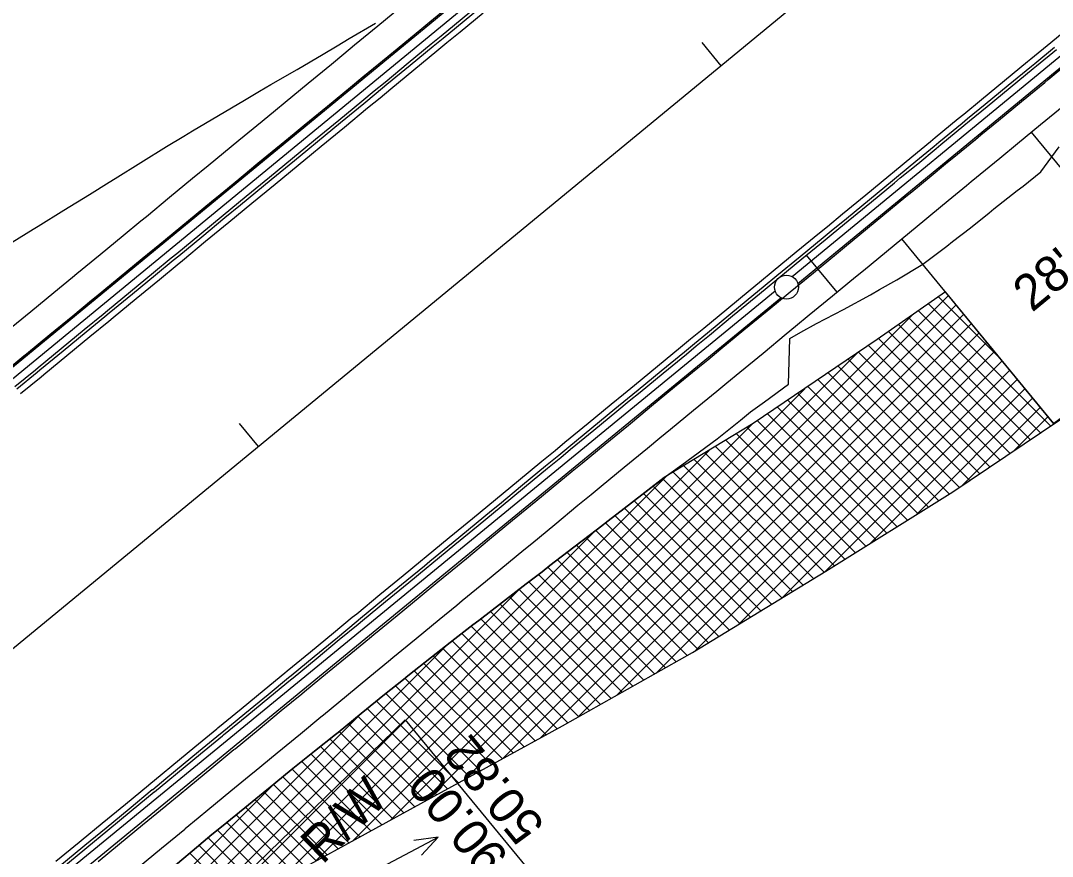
# Model space of a CAD drawing. Extents: x 1147550 to 1149124, y 2017436 to 2018779.
# Drawn here: x 1148734.8 to 1148907, y 2018327.9 to 2018467.3 of the extents above; entities that cross this region are included whole.
import ezdxf

# ---------------------------------------------------------------- set-up
doc = ezdxf.new("R2010")
doc.units = 0
for name, color, linetype in [('S_EDGE_CONCRETE', 7, 'Continuous'), ('S_ELECTRIC_UTILITIES', 7, 'Continuous'), ('S_HEADWALL', 7, 'Continuous'), ('S_IRON_PIN_ANNOT', 7, 'Continuous'), ('S_MAILBOX', 7, 'Continuous'), ('S_SECONDARY_CTL', 7, 'Continuous'), ('S_TANK', 7, 'Continuous'), ('S_TELEPHONE_UTILITIES', 7, 'Continuous'), ('S_TELEPHONE_UTILITIES_ANNOT', 7, 'Continuous')]:
    doc.layers.add(name, color=color, linetype=linetype)

msp = doc.modelspace()

# ---------------------------------------------------------------- linework, layer by layer
at = {"layer": 'S_EDGE_CONCRETE'}
msp.add_line((1148677.53, 2018316.54), (1149083.36, 2018650.43), dxfattribs=at)
for points in [[(1148848.51, 2018463.68), (1148851.69, 2018459.82)], [(1148771.29, 2018400.15), (1148774.47, 2018396.29)]]:
    msp.add_lwpolyline(points, dxfattribs=at)
at = {"layer": 'S_ELECTRIC_UTILITIES'}
msp.add_lwpolyline([(1148799.03, 2018350.69), (1148821.27, 2018323.67)], dxfattribs=at)
at = {"layer": 'S_HEADWALL'}
for p, q in [((1148929.92, 2018416.68), (1148903.54, 2018448.74)), ((1148907.31, 2018400.08), (1148881.92, 2018430.95)), ((1148871.11, 2018422.06), (1148866.02, 2018428.24))]:
    msp.add_line(p, q, dxfattribs=at)
at = {"layer": 'S_IRON_PIN_ANNOT'}
for p, q in [((1148809, 2018340.74), (1148889.72, 2018421.47)), ((1148888.02, 2018421.28), (1148898.48, 2018410.82)), ((1148815.26, 2018344.17), (1148891, 2018419.91)), ((1148884.69, 2018418.95), (1148905.07, 2018398.57)), ((1148886.36, 2018420.12), (1148906.76, 2018399.71)), ((1148802.75, 2018337.32), (1148883.66, 2018418.23)), ((1148821.51, 2018347.59), (1148892.28, 2018418.36)), ((1148827.86, 2018351.11), (1148893.55, 2018416.81)), ((1148883.03, 2018417.79), (1148903.38, 2018397.43)), ((1148834.35, 2018354.78), (1148894.83, 2018415.26)), ((1148879.7, 2018415.46), (1148900.01, 2018395.15)), ((1148881.36, 2018416.62), (1148901.7, 2018396.29)), ((1148840.85, 2018358.44), (1148896.11, 2018413.71)), ((1148878.04, 2018414.29), (1148898.32, 2018394.01)), ((1148796.51, 2018333.91), (1148874.48, 2018411.88)), ((1148847.38, 2018362.15), (1148897.38, 2018412.15)), ((1148874.67, 2018412.01), (1148894.94, 2018391.73)), ((1148876.35, 2018413.15), (1148896.63, 2018392.87)), ((1148854.65, 2018366.6), (1148898.66, 2018410.6)), ((1148872.98, 2018410.86), (1148893.25, 2018390.6)), ((1148861.92, 2018371.04), (1148899.94, 2018409.05)), ((1148869.61, 2018408.58), (1148889.85, 2018388.34)), ((1148871.3, 2018409.72), (1148891.56, 2018389.46)), ((1148867.93, 2018407.43), (1148888.11, 2018387.25)), ((1148869.2, 2018375.48), (1148901.21, 2018407.5)), ((1148790.27, 2018330.5), (1148865.7, 2018405.92)), ((1148864.55, 2018405.15), (1148884.62, 2018385.08)), ((1148866.24, 2018406.29), (1148886.37, 2018386.17)), ((1148876.68, 2018380.14), (1148902.49, 2018405.95)), ((1148862.87, 2018404.01), (1148882.88, 2018384)), ((1148884.17, 2018384.8), (1148903.77, 2018404.4)), ((1148859.5, 2018401.72), (1148879.39, 2018381.83)), ((1148861.18, 2018402.86), (1148881.14, 2018382.91)), ((1148891.85, 2018389.65), (1148905.04, 2018402.84)), ((1148900.54, 2018395.52), (1148906.32, 2018401.29)), ((1148784.04, 2018327.09), (1148856.95, 2018400.01)), ((1148857.81, 2018400.58), (1148877.65, 2018380.74)), ((1148854.32, 2018398.41), (1148874.16, 2018378.57)), ((1148856.08, 2018399.48), (1148875.91, 2018379.66)), ((1148850.8, 2018396.28), (1148870.67, 2018376.4)), ((1148852.56, 2018397.34), (1148872.42, 2018377.49)), ((1148777.91, 2018323.79), (1148849.77, 2018395.65)), ((1148849.04, 2018395.21), (1148868.93, 2018375.32)), ((1148845.52, 2018393.07), (1148865.42, 2018373.17)), ((1148847.28, 2018394.14), (1148867.17, 2018374.25)), ((1148771.86, 2018320.57), (1148842.58, 2018391.3)), ((1148842.02, 2018390.92), (1148861.91, 2018371.03)), ((1148843.76, 2018392.01), (1148863.66, 2018372.1)), ((1148840.41, 2018389.69), (1148860.15, 2018369.96)), ((1148838.81, 2018388.47), (1148858.4, 2018368.88)), ((1148835.62, 2018386), (1148854.88, 2018366.74)), ((1148837.22, 2018387.23), (1148856.64, 2018367.81)), ((1148834.02, 2018384.77), (1148853.13, 2018365.66)), ((1148832.43, 2018383.54), (1148851.37, 2018364.59)), ((1148765.8, 2018317.34), (1148830.54, 2018382.08)), ((1148829.23, 2018381.07), (1148847.86, 2018362.45)), ((1148830.83, 2018382.3), (1148849.62, 2018363.52)), ((1148827.64, 2018379.84), (1148846.08, 2018361.4)), ((1148824.44, 2018377.39), (1148842.46, 2018359.36)), ((1148826.04, 2018378.61), (1148844.27, 2018360.38)), ((1148822.84, 2018376.15), (1148840.66, 2018358.34)), ((1148821.25, 2018374.92), (1148838.85, 2018357.32)), ((1148759.75, 2018314.12), (1148818.22, 2018372.59)), ((1148818.05, 2018372.46), (1148835.23, 2018355.28)), ((1148819.65, 2018373.69), (1148837.04, 2018356.3)), ((1148816.45, 2018371.23), (1148833.42, 2018354.26)), ((1148813.25, 2018368.78), (1148829.81, 2018352.22)), ((1148814.85, 2018370), (1148831.62, 2018353.24)), ((1148811.65, 2018367.55), (1148828, 2018351.19)), ((1148810.05, 2018366.32), (1148826.19, 2018350.17)), ((1148806.86, 2018363.84), (1148822.55, 2018348.16)), ((1148808.45, 2018365.08), (1148824.37, 2018349.16)), ((1148753.78, 2018310.98), (1148805.84, 2018363.04)), ((1148805.28, 2018362.6), (1148820.72, 2018347.16)), ((1148802.12, 2018360.11), (1148817.06, 2018345.16)), ((1148803.7, 2018361.35), (1148818.89, 2018346.16)), ((1148800.53, 2018358.86), (1148815.24, 2018344.16)), ((1148798.95, 2018357.62), (1148813.41, 2018343.16)), ((1148795.82, 2018355.09), (1148809.75, 2018341.16)), ((1148797.39, 2018356.35), (1148811.58, 2018342.16)), ((1148794.26, 2018353.82), (1148807.93, 2018340.16)), ((1148747.82, 2018307.84), (1148791.81, 2018351.84)), ((1148792.7, 2018352.56), (1148806.1, 2018339.15)), ((1148789.57, 2018350.02), (1148802.44, 2018337.15)), ((1148791.13, 2018351.29), (1148804.27, 2018338.15)), ((1148788.01, 2018348.76), (1148800.61, 2018336.15)), ((1148784.88, 2018346.24), (1148796.96, 2018334.15)), ((1148786.44, 2018347.5), (1148798.79, 2018335.15)), ((1148783.31, 2018344.97), (1148795.13, 2018333.15)), ((1148781.75, 2018343.71), (1148793.3, 2018332.15)), ((1148778.62, 2018341.18), (1148789.64, 2018330.16)), ((1148780.18, 2018342.44), (1148791.47, 2018331.16)), ((1148741.85, 2018304.7), (1148777.05, 2018339.91)), ((1148777.06, 2018339.91), (1148787.81, 2018329.16)), ((1148775.5, 2018338.64), (1148785.98, 2018328.16)), ((1148772.38, 2018336.1), (1148782.33, 2018326.16)), ((1148773.94, 2018337.37), (1148784.16, 2018327.16)), ((1148770.82, 2018334.83), (1148780.49, 2018325.17)), ((1148769.26, 2018333.56), (1148778.64, 2018324.18)), ((1148766.15, 2018331.02), (1148774.95, 2018322.22)), ((1148767.7, 2018332.29), (1148776.8, 2018323.2)), ((1148764.61, 2018329.73), (1148773.11, 2018321.23)), ((1148763.08, 2018328.44), (1148771.26, 2018320.25))]:
    msp.add_line(p, q, dxfattribs=at)
for points in [[(1148725.05, 2018295.78), (1148737.29, 2018302.31), (1148759.39, 2018313.93), (1148781.46, 2018325.68), (1148803.37, 2018337.66), (1148825.28, 2018349.66), (1148846.98, 2018361.91), (1148869.23, 2018375.5), (1148890.45, 2018388.71), (1148911.17, 2018402.69), (1148932.43, 2018418.55), (1148951.91, 2018434.12), (1148970.58, 2018450.61), (1148989.32, 2018467.79), (1149007.56, 2018484.84), (1149025.52, 2018502.19), (1149043.36, 2018519.65), (1149061.14, 2018537.18), (1149078.8, 2018555.13), (1149096.46, 2018572.78), (1149114.15, 2018590.39), (1149117.96, 2018594.21)], [(1149031.17, 2018547.02), (1149027.18, 2018543.02), (1149009.16, 2018525.75), (1148991.23, 2018508.37), (1148972.44, 2018490.46), (1148954.61, 2018474.07), (1148935.64, 2018457.92), (1148916.42, 2018442.05), (1148911.86, 2018438.63), (1148929.89, 2018416.72), (1148907.28, 2018400.13), (1148889.2, 2018422.11), (1148877.8, 2018414.13), (1148857.12, 2018400.11), (1148842.25, 2018391.1)], [(1148842.25, 2018391.1), (1148839.04, 2018388.64), (1148835.08, 2018385.58), (1148833.39, 2018384.28), (1148831.12, 2018382.52), (1148827.15, 2018379.47), (1148823.18, 2018376.43), (1148821.87, 2018375.4), (1148819.23, 2018373.36), (1148815.26, 2018370.32), (1148811.29, 2018367.28), (1148810.34, 2018366.55), (1148807.33, 2018364.21), (1148803.4, 2018361.12), (1148799.47, 2018358.03), (1148798.73, 2018357.44), (1148795.58, 2018354.89), (1148791.69, 2018351.74), (1148787.81, 2018348.59), (1148787.37, 2018348.24), (1148783.91, 2018345.46), (1148780.02, 2018342.32), (1148776.14, 2018339.17), (1148775.95, 2018339.01), (1148772.27, 2018336.01), (1148768.39, 2018332.85), (1148766.77, 2018331.54), (1148764.6, 2018329.72), (1148764.53, 2018329.66), (1148760.71, 2018326.45)]]:
    msp.add_lwpolyline(points, dxfattribs=at)
at = {"layer": 'S_MAILBOX'}
msp.add_lwpolyline([(1147623.68, 2017436.42), (1147751.67, 2017548.43), (1147958.55, 2017704.02), (1148020.45, 2017753.36), (1148124.6, 2017828.73), (1148174.25, 2017853.51), (1148282.74, 2017941.53), (1148421.63, 2018031.39), (1148612.18, 2018197.22), (1148639.91, 2018214.06), (1148753.45, 2018306.48), (1148799.03, 2018350.69)], dxfattribs=at)
at = {"layer": 'S_SECONDARY_CTL'}
for points in [[(1148733.44, 2018430.41), (1148736.93, 2018432.55), (1148737.74, 2018433.06), (1148742.04, 2018435.7), (1148746.34, 2018438.35), (1148749.61, 2018440.37), (1148750.61, 2018441.02), (1148754.9, 2018443.68), (1148759.2, 2018446.32), (1148762.06, 2018448.09), (1148763.5, 2018448.97), (1148767.87, 2018451.53), (1148772.23, 2018454.1), (1148774.73, 2018455.58), (1148776.58, 2018456.67), (1148780.99, 2018459.19), (1148785.35, 2018461.76), (1148787.68, 2018463.15), (1148789.7, 2018464.34), (1148794.05, 2018466.92)], [(1148760.71, 2018326.45), (1148764.53, 2018329.66), (1148764.6, 2018329.72), (1148766.77, 2018331.54), (1148768.39, 2018332.85), (1148772.27, 2018336.01), (1148775.95, 2018339.01), (1148776.14, 2018339.17), (1148780.02, 2018342.32), (1148783.91, 2018345.46), (1148787.37, 2018348.24), (1148787.81, 2018348.59), (1148791.69, 2018351.74), (1148795.58, 2018354.89), (1148798.73, 2018357.44), (1148799.47, 2018358.03), (1148803.4, 2018361.12), (1148807.33, 2018364.21), (1148810.34, 2018366.55), (1148811.29, 2018367.28), (1148815.26, 2018370.32), (1148819.23, 2018373.36), (1148821.87, 2018375.4), (1148823.18, 2018376.43), (1148827.15, 2018379.47), (1148831.12, 2018382.52), (1148833.39, 2018384.28), (1148835.08, 2018385.58), (1148839.04, 2018388.64), (1148843.01, 2018391.68), (1148845.18, 2018393.26), (1148847.06, 2018394.63), (1148851.1, 2018397.58), (1148855.01, 2018400.7), (1148856.68, 2018402.05), (1148858.98, 2018403.74), (1148863.02, 2018406.71), (1148863.22, 2018414.33), (1148865.03, 2018415.35), (1148867.65, 2018416.82), (1148872.19, 2018419.16), (1148876.66, 2018421.61), (1148878.16, 2018422.47), (1148881.07, 2018424.12), (1148885.43, 2018426.69), (1148889.4, 2018429.73), (1148890.38, 2018430.48), (1148893.36, 2018432.78), (1148896.47, 2018435.3), (1148897.25, 2018435.93), (1148901.19, 2018439), (1148902.15, 2018439.73), (1148905.09, 2018442.14), (1148908.17, 2018446.27)]]:
    msp.add_lwpolyline(points, dxfattribs=at)
at = {"layer": 'S_TANK'}
for p, q in [((1148793.41, 2018325.23), (1148804.51, 2018331.13)), ((1148804.51, 2018331.13), (1148800.45, 2018330.56)), ((1148804.51, 2018331.13), (1148801.77, 2018328.09))]:
    msp.add_line(p, q, dxfattribs=at)
at = {"layer": 'S_TELEPHONE_UTILITIES'}
msp.add_line((1148654.34, 2018344.72), (1148896.46, 2018543.92), dxfattribs=at)
for points in [[(1148731.97, 2018408.59), (1148735.4, 2018411.41), (1148735.83, 2018411.77), (1148739.69, 2018414.95), (1148743.55, 2018418.12), (1148746.68, 2018420.7), (1148747.42, 2018421.3), (1148751.28, 2018424.48), (1148755.14, 2018427.65), (1148758.08, 2018430.07), (1148759, 2018430.83), (1148762.86, 2018434.01), (1148766.72, 2018437.18), (1148769.29, 2018439.3), (1148770.58, 2018440.36), (1148774.44, 2018443.54), (1148778.3, 2018446.71), (1148780.52, 2018448.54), (1148782.17, 2018449.89), (1148786.03, 2018453.07), (1148789.89, 2018456.24), (1148791.96, 2018457.95), (1148793.75, 2018459.42), (1148797.61, 2018462.6), (1148801.47, 2018465.77), (1148803.13, 2018467.14), (1148805.33, 2018468.95)], [(1148732.66, 2018415.63), (1148736.52, 2018418.81), (1148740.38, 2018421.98), (1148743.51, 2018424.56), (1148744.24, 2018425.16), (1148748.1, 2018428.34), (1148751.96, 2018431.51), (1148754.9, 2018433.93), (1148755.82, 2018434.69), (1148759.68, 2018437.87), (1148763.54, 2018441.04), (1148766.12, 2018443.16), (1148767.41, 2018444.22), (1148771.27, 2018447.4), (1148775.13, 2018450.57), (1148777.35, 2018452.4), (1148778.99, 2018453.75), (1148782.85, 2018456.93), (1148786.71, 2018460.1), (1148788.78, 2018461.81), (1148790.57, 2018463.28), (1148794.43, 2018466.46), (1148798.29, 2018469.63)], [(1148733.88, 2018406.28), (1148737.3, 2018409.09), (1148737.74, 2018409.45), (1148741.6, 2018412.63), (1148745.46, 2018415.81), (1148748.59, 2018418.38), (1148749.32, 2018418.98), (1148753.18, 2018422.16), (1148757.04, 2018425.34), (1148759.98, 2018427.75), (1148760.9, 2018428.51), (1148764.77, 2018431.69), (1148768.63, 2018434.87), (1148771.2, 2018436.98), (1148772.49, 2018438.04), (1148776.35, 2018441.22), (1148780.21, 2018444.4), (1148782.43, 2018446.22), (1148784.07, 2018447.57), (1148787.93, 2018450.75), (1148791.79, 2018453.93), (1148793.87, 2018455.63), (1148795.66, 2018457.1), (1148799.52, 2018460.28), (1148803.38, 2018463.46), (1148805.04, 2018464.82), (1148807.24, 2018466.63), (1148811.1, 2018469.81)], [(1148734.19, 2018405.89), (1148737.62, 2018408.71), (1148738.06, 2018409.07), (1148741.92, 2018412.24), (1148745.78, 2018415.42), (1148748.91, 2018417.99), (1148749.64, 2018418.6), (1148753.5, 2018421.77), (1148757.36, 2018424.95), (1148760.3, 2018427.37), (1148761.22, 2018428.13), (1148765.08, 2018431.3), (1148768.94, 2018434.48), (1148771.52, 2018436.6), (1148772.81, 2018437.66), (1148776.67, 2018440.83), (1148780.53, 2018444.01), (1148782.75, 2018445.84), (1148784.39, 2018447.19), (1148788.25, 2018450.36), (1148792.11, 2018453.54), (1148794.18, 2018455.24), (1148795.97, 2018456.72), (1148799.83, 2018459.89), (1148803.7, 2018463.07), (1148805.36, 2018464.44), (1148807.56, 2018466.25), (1148811.42, 2018469.42)], [(1148734.83, 2018405.12), (1148738.26, 2018407.94), (1148738.69, 2018408.29), (1148742.55, 2018411.47), (1148746.41, 2018414.65), (1148749.54, 2018417.22), (1148750.27, 2018417.82), (1148754.14, 2018421), (1148758, 2018424.18), (1148760.94, 2018426.6), (1148761.86, 2018427.35), (1148765.72, 2018430.53), (1148769.58, 2018433.71), (1148772.15, 2018435.82), (1148773.44, 2018436.88), (1148777.3, 2018440.06), (1148781.16, 2018443.24), (1148783.38, 2018445.06), (1148785.02, 2018446.41), (1148788.89, 2018449.59), (1148792.75, 2018452.77), (1148794.82, 2018454.47), (1148796.61, 2018455.94), (1148800.47, 2018459.12), (1148804.33, 2018462.3), (1148805.99, 2018463.67), (1148808.19, 2018465.47), (1148812.05, 2018468.65)], [(1148740.74, 2018327.1), (1148744.6, 2018330.28), (1148744.92, 2018330.54), (1148748.46, 2018333.46), (1148752.32, 2018336.63), (1148756.19, 2018339.81), (1148756.25, 2018339.86), (1148758.44, 2018341.67), (1148760.05, 2018342.99), (1148763.91, 2018346.16), (1148767.58, 2018349.19), (1148767.77, 2018349.34), (1148771.63, 2018352.52), (1148775.49, 2018355.69), (1148778.92, 2018358.51), (1148779.35, 2018358.87), (1148783.21, 2018362.05), (1148787.08, 2018365.22), (1148790.2, 2018367.8), (1148790.94, 2018368.4), (1148794.8, 2018371.58), (1148798.66, 2018374.75), (1148801.6, 2018377.17), (1148802.52, 2018377.93), (1148806.38, 2018381.11), (1148810.24, 2018384.29), (1148812.81, 2018386.4), (1148814.1, 2018387.46), (1148817.96, 2018390.64), (1148821.83, 2018393.82), (1148824.04, 2018395.64), (1148825.69, 2018396.99), (1148829.55, 2018400.17), (1148833.41, 2018403.35), (1148835.48, 2018405.05), (1148837.27, 2018406.52), (1148841.13, 2018409.7), (1148844.99, 2018412.88), (1148846.65, 2018414.24), (1148848.85, 2018416.05), (1148852.71, 2018419.23), (1148856.58, 2018422.41), (1148858.15, 2018423.7), (1148860.44, 2018425.58), (1148864.3, 2018428.76), (1148868.16, 2018431.94), (1148869.48, 2018433.02), (1148872.02, 2018435.11), (1148875.88, 2018438.29), (1148879.74, 2018441.47), (1148880.7, 2018442.25), (1148883.6, 2018444.64), (1148886.69, 2018447.18), (1148887.47, 2018447.82), (1148891.33, 2018451), (1148892.25, 2018451.76), (1148895.19, 2018454.17), (1148899.05, 2018457.35), (1148902.91, 2018460.53), (1148903.46, 2018460.98), (1148906.77, 2018463.7), (1148910.63, 2018466.88)], [(1148741.38, 2018326.33), (1148745.24, 2018329.51), (1148745.55, 2018329.77), (1148749.1, 2018332.69), (1148752.96, 2018335.86), (1148756.82, 2018339.04), (1148756.88, 2018339.09), (1148759.08, 2018340.89), (1148760.68, 2018342.22), (1148764.54, 2018345.39), (1148768.22, 2018348.41), (1148768.4, 2018348.57), (1148772.27, 2018351.75), (1148776.13, 2018354.92), (1148779.55, 2018357.74), (1148779.99, 2018358.1), (1148783.85, 2018361.28), (1148787.71, 2018364.45), (1148790.84, 2018367.03), (1148791.57, 2018367.63), (1148795.43, 2018370.81), (1148799.29, 2018373.98), (1148802.23, 2018376.4), (1148803.16, 2018377.16), (1148807.02, 2018380.34), (1148810.88, 2018383.51), (1148813.45, 2018385.63), (1148814.74, 2018386.69), (1148818.6, 2018389.87), (1148822.46, 2018393.04), (1148824.68, 2018394.87), (1148826.32, 2018396.22), (1148830.18, 2018399.4), (1148834.04, 2018402.57), (1148836.12, 2018404.28), (1148837.91, 2018405.75), (1148841.77, 2018408.93), (1148845.63, 2018412.1), (1148847.29, 2018413.47), (1148849.49, 2018415.28), (1148853.35, 2018418.46), (1148857.21, 2018421.63), (1148858.79, 2018422.93), (1148861.07, 2018424.81), (1148864.93, 2018427.99), (1148868.79, 2018431.16), (1148870.11, 2018432.25), (1148872.66, 2018434.34), (1148876.52, 2018437.52), (1148880.38, 2018440.69), (1148881.34, 2018441.48), (1148884.24, 2018443.87), (1148887.33, 2018446.41), (1148888.1, 2018447.05), (1148891.96, 2018450.22), (1148892.89, 2018450.99), (1148895.82, 2018453.4), (1148899.68, 2018456.58), (1148903.55, 2018459.75), (1148904.09, 2018460.2), (1148907.41, 2018462.93)], [(1148741.69, 2018325.95), (1148745.56, 2018329.12), (1148745.87, 2018329.38), (1148749.42, 2018332.3), (1148753.28, 2018335.48), (1148757.14, 2018338.65), (1148757.2, 2018338.7), (1148759.39, 2018340.51), (1148761, 2018341.83), (1148764.86, 2018345.01), (1148768.53, 2018348.03), (1148768.72, 2018348.18), (1148772.58, 2018351.36), (1148776.44, 2018354.54), (1148779.87, 2018357.35), (1148780.31, 2018357.71), (1148784.17, 2018360.89), (1148788.03, 2018364.07), (1148791.16, 2018366.64), (1148791.89, 2018367.24), (1148795.75, 2018370.42), (1148799.61, 2018373.6), (1148802.55, 2018376.01), (1148803.47, 2018376.77), (1148807.33, 2018379.95), (1148811.2, 2018383.13), (1148813.77, 2018385.24), (1148815.06, 2018386.3), (1148818.92, 2018389.48), (1148822.78, 2018392.66), (1148825, 2018394.48), (1148826.64, 2018395.83), (1148830.5, 2018399.01), (1148834.36, 2018402.19), (1148836.43, 2018403.89), (1148838.22, 2018405.36), (1148842.08, 2018408.54), (1148845.95, 2018411.72), (1148847.61, 2018413.08), (1148849.81, 2018414.89), (1148853.67, 2018418.07), (1148857.53, 2018421.25), (1148859.1, 2018422.54), (1148861.39, 2018424.42), (1148865.25, 2018427.6), (1148869.11, 2018430.78), (1148870.43, 2018431.86), (1148872.97, 2018433.95), (1148876.83, 2018437.13), (1148880.7, 2018440.31), (1148881.65, 2018441.1), (1148884.56, 2018443.48), (1148887.65, 2018446.03), (1148888.42, 2018446.66), (1148892.28, 2018449.84), (1148893.21, 2018450.6), (1148896.14, 2018453.01), (1148900, 2018456.19), (1148903.86, 2018459.37), (1148904.41, 2018459.82), (1148907.72, 2018462.54)], [(1148747.78, 2018327.07), (1148751.32, 2018329.98), (1148755.18, 2018333.16), (1148759.05, 2018336.34), (1148759.11, 2018336.39), (1148761.3, 2018338.19), (1148762.91, 2018339.51), (1148766.77, 2018342.69), (1148770.44, 2018345.71), (1148770.63, 2018345.87), (1148774.49, 2018349.04), (1148778.35, 2018352.22), (1148781.78, 2018355.04), (1148782.21, 2018355.4), (1148786.07, 2018358.57), (1148789.93, 2018361.75), (1148793.06, 2018364.32), (1148793.8, 2018364.93), (1148797.66, 2018368.1), (1148801.52, 2018371.28), (1148804.46, 2018373.7), (1148805.38, 2018374.46), (1148809.24, 2018377.63), (1148813.1, 2018380.81), (1148815.67, 2018382.93), (1148816.96, 2018383.99), (1148820.82, 2018387.16), (1148824.68, 2018390.34), (1148826.9, 2018392.17), (1148828.55, 2018393.52), (1148832.41, 2018396.69), (1148836.27, 2018399.87), (1148838.34, 2018401.57), (1148840.13, 2018403.05), (1148843.99, 2018406.22), (1148847.85, 2018409.4), (1148849.51, 2018410.77), (1148851.71, 2018412.58), (1148855.57, 2018415.75), (1148859.44, 2018418.93), (1148861.01, 2018420.23), (1148863.3, 2018422.11), (1148867.16, 2018425.28), (1148871.02, 2018428.46), (1148872.34, 2018429.54), (1148874.88, 2018431.64), (1148878.74, 2018434.81), (1148882.6, 2018437.99), (1148883.56, 2018438.78), (1148886.46, 2018441.17), (1148889.55, 2018443.71), (1148890.32, 2018444.34), (1148894.19, 2018447.52), (1148895.11, 2018448.28), (1148898.05, 2018450.7), (1148901.91, 2018453.87), (1148905.77, 2018457.05), (1148906.32, 2018457.5), (1148909.63, 2018460.23)], [(1148754.5, 2018326.12), (1148758.36, 2018329.3), (1148762.22, 2018332.47), (1148762.28, 2018332.53), (1148764.48, 2018334.33), (1148766.08, 2018335.65), (1148769.94, 2018338.83), (1148773.62, 2018341.85), (1148773.81, 2018342.01), (1148777.67, 2018345.18), (1148781.53, 2018348.36), (1148784.95, 2018351.18), (1148785.39, 2018351.54), (1148789.25, 2018354.71), (1148793.11, 2018357.89), (1148796.24, 2018360.46), (1148796.97, 2018361.07), (1148800.83, 2018364.24), (1148804.69, 2018367.42), (1148807.63, 2018369.84), (1148808.56, 2018370.6), (1148812.42, 2018373.77), (1148816.28, 2018376.95), (1148818.85, 2018379.07), (1148820.14, 2018380.13), (1148824, 2018383.3), (1148827.86, 2018386.48), (1148830.08, 2018388.3), (1148831.72, 2018389.66), (1148835.58, 2018392.83), (1148839.44, 2018396.01), (1148841.52, 2018397.71), (1148843.31, 2018399.19), (1148847.17, 2018402.36), (1148851.03, 2018405.54), (1148852.69, 2018406.91), (1148854.89, 2018408.72), (1148858.75, 2018411.89), (1148862.61, 2018415.07), (1148864.19, 2018416.37), (1148866.47, 2018418.25), (1148870.33, 2018421.42), (1148874.2, 2018424.6), (1148875.51, 2018425.68), (1148878.06, 2018427.78), (1148881.92, 2018430.95), (1148885.78, 2018434.13), (1148886.74, 2018434.92), (1148889.64, 2018437.31), (1148892.73, 2018439.85), (1148893.5, 2018440.48), (1148897.36, 2018443.66), (1148898.29, 2018444.42), (1148901.22, 2018446.84), (1148905.08, 2018450.01), (1148908.95, 2018453.19)]]:
    msp.add_lwpolyline(points, dxfattribs=at)
at = {"layer": 'S_TELEPHONE_UTILITIES_ANNOT'}
for p, q in [((1148863.62, 2018424.64), (1149080.84, 2018603.35)), ((1148863.62, 2018424.64), (1149080.84, 2018603.35)), ((1148864.57, 2018423.48), (1149081.79, 2018602.19)), ((1148864.57, 2018423.48), (1149081.79, 2018602.19)), ((1148644.81, 2018336.58), (1148873.56, 2018524.76)), ((1148644.81, 2018336.58), (1148873.56, 2018524.76)), ((1148645.77, 2018335.43), (1148874.51, 2018523.6)), ((1148645.77, 2018335.43), (1148874.51, 2018523.6)), ((1148642.87, 2018243.65), (1148860.75, 2018422.28)), ((1148642.87, 2018243.65), (1148860.75, 2018422.28)), ((1148643.82, 2018242.49), (1148861.7, 2018421.12)), ((1148643.82, 2018242.49), (1148861.7, 2018421.12))]:
    msp.add_line(p, q, dxfattribs=at)
msp.add_circle((1148862.66, 2018422.88), 2, dxfattribs=at)

# ---------------------------------------------------------------- texts
at = {"layer": 'S_ELECTRIC_UTILITIES'}
for s, p in [('50.82', (1148822.53, 2018333.15)), ('+90.00', (1148819.48, 2018324.26))]:
    msp.add_text(s, height=6, rotation=129.4453, dxfattribs=at).set_placement(p)
at = {"layer": 'S_HEADWALL'}
msp.add_text("28'", height=6, rotation=39.4453, dxfattribs=at).set_placement((1148903.64, 2018418.57))
at = {"layer": 'S_MAILBOX'}
msp.add_text('PROP. R/W', height=6, rotation=44.1276, dxfattribs=at).set_placement((1148765.68, 2018307.48))

doc.saveas('drawing.dxf')
